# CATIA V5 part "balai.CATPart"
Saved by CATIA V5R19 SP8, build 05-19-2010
Part number: balai
Bounding box of the stored display mesh (mm): x -12.149 to 7.851, y 134.496 to 350.571, z 8.504 to 129.493
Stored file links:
  G:\EU_thinkMotion\CFAO_2010\MMS_groupe3\MMS_groupe3\A reprendre\amenand\amenand\balai.CATPart
  F:\thinkmotion CFAO v12.1\essuie_glace.CATProduct
  G:\EU_thinkMotion\CFAO_2010\MMS_groupe3\MMS_groupe3\A reprendre\amenand\amenand\biellette3.CATPart
  G:\EU_thinkMotion\CFAO_2010\MMS_groupe3\MMS_groupe3\A reprendre\amenand\amenand\couronne.CATPart
  G:\EU_thinkMotion\CFAO_2010\MMS_groupe3\MMS_groupe3\A reprendre\amenand\amenand\coulisseau.CATPart
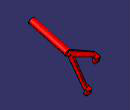
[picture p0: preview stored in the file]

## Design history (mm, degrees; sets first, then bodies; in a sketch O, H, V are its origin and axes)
Set1
  Plane1: linked copy from another document
  Point1: linked copy from another document
  Plane2: linked copy from another document
  Line1: linked copy from another document
  Plane3: linked copy from another document
  Point2: linked copy from another document
  Plane4 to Plane6: linked copy from another document
  DatumSurface1: linked copy from another document
  DatumSurface2: linked copy from another document
Body1 (main body)
  Sketch1 on Plane1, origin (-2.1488, 302.7802, 88.354), H (0, 1, 0), V (0, 0, 1)
    circle A1 centre (-42.7425, -2.1301) radius 2
    point P1 (-42.7425, -2.1301)
    reference projected point E1 (-42.7425, -2.1301) from Point1
    radius A1 = 2
    coincidence: P1 E1
  Pad1: profile Sketch1, direction (1, 0, 0), up to Plane2
  Sketch2 on Plane4, origin (0, 38.1911, 144.7545), H (-1, 0, 0), V (0, -0.9669, 0.2551)
    line L1 (-7.8512, -298.6449) -> (-7.8512, -308.7599)
    line L2 (-7.8512, -308.7599) -> (7.1488, -306.4781)
    line L3 (7.1488, -306.4781) -> (7.1488, -220.3273)
    line L4 (7.1488, -220.3273) -> (2.1488, -221.0879)
    line L5 (2.1488, -221.0879) -> (2.1488, -297.1237)
    line L6 (2.1488, -297.1237) -> (-7.8512, -298.6449)
    reference projected point E1 (2.1488, -221.0879) from Sketch3.L1
    reference projected point E2 (2.1488, -307.2387) from Sketch3.L2
    reference intersected line E3 through (-7.8512, 0) direction (0, -1) from Plane5
    distance L5 L3 = 5
    distance L1 L3 = 15
    distance L2 L6 = 10
    parallelism: L4 L2, L5 L1
    coincidence: L4 E1, E2 L2, E3 L1
  Sketch3 on Plane1, origin (-2.1488, 0, 0), H (0, 1, 0), V (0, 0, 1)
    line L1 (253.8773, 95.6059) -> (250.0507, 81.1021)
    point P1 (253.8773, 95.6059)
    reference projected line E1 (251.964, 88.354) -> (203.6183, 101.1092) from Line1
    reference projected line E2 (251.964, 88.354) -> (203.6183, 101.1092) from Line1
    line L2 (350.5707, 124.3913) -> (346.7441, 109.8876)
    point P4 (346.7441, 109.8876)
    line L3 (323.8223, 23.0077) -> (319.9957, 8.504)
    point P5 (323.8223, 23.0077)
    line L4 (350.5707, 124.3913) -> (331.2324, 129.4934)
    line L5 (346.7441, 109.8876) -> (327.4059, 114.9897)
    point P8 (346.7441, 109.8876)
    line L6 (323.8223, 23.0077) -> (304.484, 28.1098)
    point P10 (323.8223, 23.0077)
    point P11 (304.484, 28.1098)
    line L7 (319.9957, 8.504) -> (300.6574, 13.6061)
    reference intersected line E3 through (301.9079, -79.6535) direction (-0.2551, -0.9669) from Plane3
    line L8 (250.0507, 81.1021) -> (300.6574, 13.6061)
    line L9 (253.8773, 95.6059) -> (331.2324, 129.4934)
    line L10 (327.4059, 114.9897) -> (266.4677, 84.5274)
    point P13 (266.4677, 84.5274)
    reference projected line E4 (251.964, 88.354) -> (203.6183, 101.1092) from Line1
    line L11 (304.484, 28.1098) -> (266.4677, 84.5274)
    point P14 (304.484, 28.1098)
    point P15 (266.4677, 84.5274)
    reference projected point E5 (251.964, 88.354) from Point2
    reference intersected line E6 (355.4053, 123.1158) -> (268.3831, 146.0752) from face of DatumSurface1
    reference intersected line E7 (237.7789, 30.1956) -> (324.8303, 7.2285) from face of DatumSurface2
    length L1 = 15
    distance P1 E2 = 7.5
    distance L6 L7 = 15
    distance L4 L5 = 15
    distance L2 E3 = 5
    length L5 = 20
    length L4 = 20
    length L6 = 20
    length L7 = 20
    distance P13 L1 = 15
    perpendicularity: L1 E1, L4 L3
    parallelism: L2 L1, L3 L2, L7 L5
    coincidence: P5 L2, P8 L2, P10 P5, P4 P8, P13 E4, P14 L6, P15 P13, L1 E5, P14 P11, L4 E6, L7 E7
  SolidCombine1: FirstComponentProfile Sketch2, FirstComponentDirection Sketch2, SecondComponentProfile Sketch3, SecondComponentDirection Sketch3
  Sketch4 on Plane6, origin (-3.5728, 161.1396, 209.9894), H (1, 0, 0), V (0, 0.2551, 0.9669)
    circle A1 centre (1.4239, -94.4412) radius 10
    point P1 (1.4239, -94.4412)
    reference projected point E1 (1.4239, -94.4412) from Line1
    radius A1 = 10
    coincidence: P1 E1
  Pad2: profile Sketch4, direction (0, 0.9669, -0.2551), up to face of SolidCombine1 from Sketch3.L1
